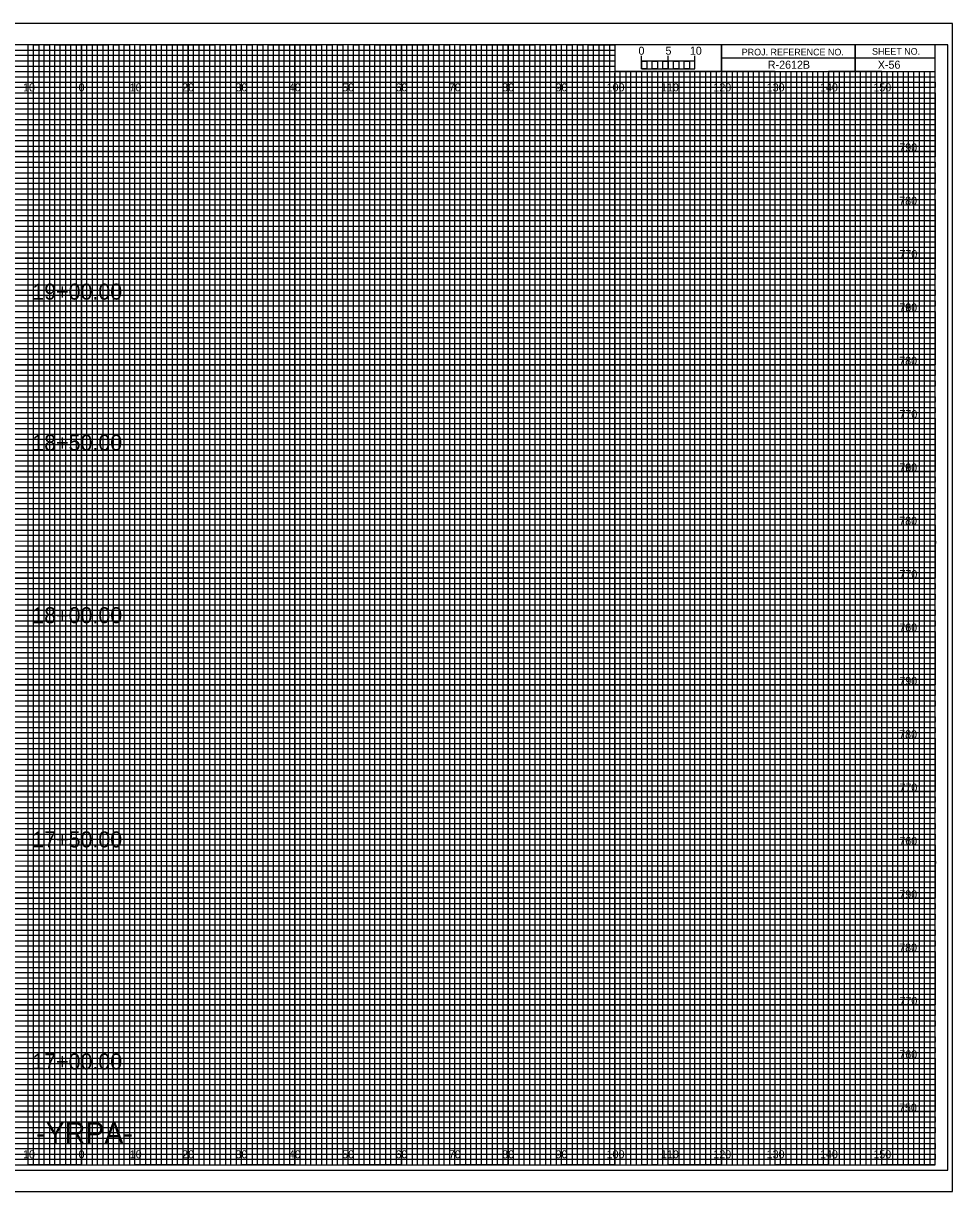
# Model space of a CAD drawing. Extents: x -13 to 323, y 655 to 874.
# Drawn here: x 149.1 to 323.3, y 655 to 874 of the extents above; entities that cross this region are included whole.
import ezdxf

# ---------------------------------------------------------------- set-up
doc = ezdxf.new("R2010")
doc.units = 0
for name, color, linetype in [('Exist Cross Section Cell', 7, 'Continuous'), ('Exist XS Ground Line', 7, 'Continuous'), ('Prop XS Ditch Slope Text', 7, 'Continuous'), ('Prop XS Ditch Standard Text', 7, 'Continuous'), ('Prop XS Dump Level', 7, 'Continuous'), ('Prop XS EOT Tick Mark', 7, 'Continuous'), ('Prop XS Finish Grade', 7, 'Continuous'), ('Prop XS Finish Grade Earthwork', 7, 'Continuous'), ('Prop XS Finish Grade Paved Shoulder', 7, 'Continuous'), ('Prop XS Finish Grade Pavement', 7, 'Continuous'), ('Prop XS Guardrail', 7, 'Continuous'), ('Prop XS Hydro Fill Slope Data', 7, 'Continuous'), ('Prop XS Pvmt Edge Slope', 7, 'Continuous'), ('Prop XS SE Text', 7, 'Continuous'), ('Prop XS Side Slope Text', 7, 'Continuous'), ('Prop XS SS Elevation Text', 7, 'Continuous'), ('Prop XS Subgrade Earthwork', 7, 'Continuous')]:
    doc.layers.add(name, color=color, linetype=linetype)

msp = doc.modelspace()

# ---------------------------------------------------------------- linework, layer by layer
at = {"layer": 'Exist XS Ground Line'}
for p, q in [((150, 870), (140, 870)), ((150, 660), (150, 870)), ((170, 870), (160, 870)), ((160, 870), (160, 660)), ((170, 660), (170, 870)), ((190, 870), (180, 870)), ((180, 870), (180, 660)), ((190, 660), (190, 870)), ((210, 870), (200, 870)), ((200, 870), (200, 660)), ((210, 660), (210, 870)), ((230, 870), (220, 870)), ((220, 870), (220, 660)), ((230, 660), (230, 870)), ((250, 870), (240, 870)), ((240, 870), (240, 660)), ((250, 660), (250, 870)), ((260, 870), (260, 660)), ((270, 660), (270, 865)), ((290, 865), (280, 865)), ((280, 865), (280, 660)), ((290, 660), (290, 865)), ((310, 865), (300, 865)), ((300, 865), (300, 660)), ((310, 660), (310, 865)), ((160, 660), (150, 660)), ((180, 660), (170, 660)), ((200, 660), (190, 660)), ((220, 660), (210, 660)), ((240, 660), (230, 660)), ((260, 660), (250, 660)), ((280, 660), (270, 660)), ((300, 660), (290, 660)), ((320, 660), (310, 660)), ((320, 660), (320, 660))]:
    msp.add_line(p, q, dxfattribs=at)
for points in [[(0, 860), (320, 860), (320, 850), (0, 850)], [(0, 840), (320, 840), (320, 830), (0, 830)], [(0, 820), (320, 820), (320, 810), (0, 810)], [(0, 800), (320, 800), (320, 790), (0, 790)], [(0, 780), (320, 780), (320, 770), (0, 770)], [(0, 760), (320, 760), (320, 750), (0, 750)], [(0, 740), (320, 740), (320, 730), (0, 730)], [(0, 720), (320, 720), (320, 710), (0, 710)], [(0, 700), (320, 700), (320, 690), (0, 690)], [(0, 680), (320, 680), (320, 670), (0, 670)]]:
    msp.add_lwpolyline(points, dxfattribs=at)
at = {"layer": 'Prop XS Ditch Slope Text'}
for p, q in [((305, 870), (305, 865)), ((305, 865), (305, 870)), ((280, 867.5), (280, 865)), ((320, 867.49), (280, 867.49)), ((280, 865), (320, 865))]:
    msp.add_line(p, q, dxfattribs=at)
for points in [[(320, 870), (0, 870), (0, 660), (320, 660)], [(280, 870), (260, 870), (260, 865.03), (280, 865.03)], [(320, 870), (280, 870), (280, 865), (320, 865)]]:
    msp.add_lwpolyline(points, close=True, dxfattribs=at)
at = {"layer": 'Prop XS Ditch Standard Text'}
for p, q in [((0, 869), (260, 869)), ((260, 867.98), (0, 867.98)), ((260, 869), (260, 867.98)), ((0, 867), (260, 867)), ((260, 865.89), (0, 865.89)), ((260, 867), (260, 865.89)), ((0, 864), (320, 864))]:
    msp.add_line(p, q, dxfattribs=at)
for points in [[(0, 863), (270, 863), (320, 863), (320, 862), (0, 862)], [(0, 861), (320, 861), (320, 859), (0, 859)], [(0, 858), (320, 858), (320, 857), (0, 856.98)], [(0, 856), (320, 856), (320, 854), (0, 854)], [(0, 853), (320, 853), (320, 852), (0, 852)], [(0, 851), (320, 851), (320, 849), (0, 849)], [(0, 848), (320, 848), (320, 847), (0, 847)], [(0, 846), (320, 846), (320, 844), (0, 844)], [(0, 843), (320, 843), (320, 842), (0, 842)], [(0, 841), (320, 841), (320, 839), (0, 839)], [(0, 838), (320, 838), (320, 837), (0, 837)], [(0, 836), (320, 836), (320, 833.95), (320, 833), (320, 832), (0, 832)], [(0, 834), (320, 834), (320, 833), (0, 833)], [(0, 831), (320, 831), (320, 829), (0, 829.03)], [(0, 829.03), (320, 829), (320, 828), (0, 828)], [(0, 827), (320, 827), (320, 826), (0, 826)], [(0, 824), (320, 824), (320, 823), (0, 823)], [(0, 822), (320, 822), (320, 821), (0, 821)], [(-0.07, 818.89), (320, 818.89), (320, 817.88), (-0.07, 817.88)], [(0, 817), (320, 817), (320, 816), (0, 816)], [(0, 814), (320, 814), (320, 813), (0, 813)], [(0, 812), (320, 812), (320, 811), (0, 811)], [(0, 809), (320, 809), (320, 808), (0, 808)], [(0, 807), (320, 807), (320, 806), (0, 806)], [(0, 804), (320, 804), (320, 803), (0, 803)], [(0, 802), (320, 802), (320, 801), (0, 801)], [(0, 799), (320, 799), (319.99, 797.98), (0, 798)], [(0, 797), (320, 797), (320, 796), (0, 796)], [(0, 794), (320, 794), (320, 793), (0, 793)], [(0, 792), (320, 792), (320, 791), (0, 791)], [(0, 789), (320, 789), (320, 788), (0, 788)], [(0, 787), (320, 787), (320, 786), (0, 786)], [(0, 784), (320, 784), (320, 783), (0, 783)], [(0, 782), (320, 782), (320, 781), (0, 781)], [(0, 779), (320, 779), (320, 778), (0, 778)], [(0, 776.99), (320.07, 776.91), (320, 776), (0, 776)], [(0, 774), (320, 774), (320, 773), (0, 773)], [(0, 772), (320, 772), (320, 771), (0, 771)], [(0, 769), (320, 769), (320, 768), (0, 768)], [(0, 767), (320, 767), (320, 766), (0, 766)], [(0, 764), (320, 764), (320, 763), (0, 763)], [(0, 762), (320, 762), (320, 761), (0, 761)], [(0, 759), (320, 759), (320, 758), (0, 758)], [(0, 757), (320, 757), (320, 756), (0, 756)], [(0, 754), (320, 754), (320, 753), (0, 753)], [(0, 752), (320, 752), (320, 751), (0, 751)], [(0, 749), (320, 749), (320, 748), (0, 748)], [(0, 747), (320, 747), (320, 746), (0, 746)], [(0, 744), (320, 744), (320, 743), (0, 743)], [(0, 742), (320, 742), (320, 741), (0, 741)], [(0, 739), (320, 739), (319.99, 737.98), (0, 738)], [(0, 737), (320, 737), (320, 736), (0, 736)], [(0, 734), (320, 734), (320, 733), (0, 733)], [(0, 732), (320, 732), (320, 731), (0, 731)], [(0, 729), (320, 729), (320, 728), (0, 728)], [(0, 727), (320, 727), (320, 726), (0, 726)], [(0, 724), (320, 724), (320, 723), (0, 723)], [(0, 722), (320, 722), (320, 721), (0, 721)], [(0, 719), (320, 719), (320, 718), (0, 718)], [(0, 716.99), (320.07, 716.91), (320, 716), (0, 716)], [(0, 714), (320, 714), (320, 713), (0, 713)], [(0, 712), (320, 712), (320, 711), (0, 711)], [(0, 709), (320, 709), (320, 708), (0, 708)], [(0, 707), (320, 707), (320, 706), (0, 706)], [(0, 704), (320, 704), (320, 703), (0, 703)], [(0, 702), (320, 702), (320, 701), (0, 701)], [(0, 699), (320, 699), (320, 698), (0, 698)], [(0, 697), (320, 697), (320, 696), (0, 696)], [(0, 694), (320, 694), (320, 693), (0, 693)], [(0, 692), (320, 692), (320, 691), (0, 691)], [(0, 689), (320, 689), (320, 688), (0, 688)], [(0, 687), (320, 687), (320, 686), (0, 686)], [(0, 684), (320, 684), (320, 683), (0, 683)], [(0, 682), (320, 682), (320, 681), (0, 681)], [(0, 679), (320, 679), (320, 678), (0, 678)], [(0, 677), (320, 677), (320, 676), (0, 676)], [(0, 674), (320, 674), (320, 673), (0, 673)], [(0, 672), (320, 672), (320, 671), (0, 671)], [(0, 669), (320, 669), (320, 668), (0, 668)], [(0, 667), (320, 667), (320, 666), (0, 666)], [(0, 664), (320, 664), (320, 663), (0, 663)], [(0, 662), (320, 662), (320, 661), (0, 661)]]:
    msp.add_lwpolyline(points, dxfattribs=at)
at = {"layer": 'Prop XS Dump Level'}
for points in [[(145, 660), (155, 660), (155, 870), (165, 870), (165, 660), (175, 660), (175, 870), (185, 870), (185, 660), (195, 660), (195, 870), (205, 870), (205, 660), (215, 660), (215, 870), (225, 870), (225, 660), (235, 660), (235, 870), (245, 870), (245, 660), (255, 660), (255, 870), (259.93, 870), (260, 870), (260, 865), (264.99, 865), (264.99, 660), (275, 660), (275, 865), (285, 865), (285, 660), (295, 660), (295, 865), (305, 865), (305, 660), (315, 660), (315, 865)], [(0, 865), (275, 865)], [(0, 845), (320, 845), (320, 855), (0, 855)], [(0, 825), (320, 825), (320, 835), (0, 835)], [(0, 805), (320, 805), (320, 815), (0, 815)], [(0, 785), (320, 785), (320, 795), (0, 795)], [(0, 765), (320, 765), (320, 775), (0, 775)], [(0, 745), (320, 745), (320, 755), (0, 755)], [(0, 725), (320, 725), (320, 735), (0, 735)], [(0, 705), (320, 705), (320, 715), (0, 715)], [(0, 685), (320, 685), (320, 695), (0, 695)], [(0, 665), (320, 665), (320, 675), (0, 675)]]:
    msp.add_lwpolyline(points, dxfattribs=at)
at = {"layer": 'Prop XS Finish Grade'}
for p, q in [((150, 660), (150, 870)), ((160, 660), (160, 870)), ((170, 660), (170, 870)), ((180, 660), (180, 870)), ((190, 660), (190, 870)), ((200, 660), (200, 870)), ((210, 660), (210, 870)), ((220, 660), (220, 870)), ((230, 660), (230, 870)), ((240, 660), (240, 870)), ((250, 660), (250, 870)), ((260, 660), (260, 864.69)), ((270, 660), (270, 864.69)), ((280, 660), (280, 864.69)), ((290, 660), (290, 864.69)), ((300, 660), (300, 864.69)), ((310, 660), (310, 864.69)), ((0, 860), (320, 860)), ((0, 850), (320, 850)), ((0, 840), (320, 840)), ((0, 830), (320, 830)), ((0, 820), (320, 820)), ((0, 810), (320, 810)), ((0, 800), (320, 800)), ((0, 790), (320, 790)), ((0, 780), (320, 780)), ((0, 770), (320, 770)), ((0, 760), (320, 760)), ((0, 750), (320, 750)), ((0, 740), (320, 740)), ((0, 730), (320, 730)), ((0, 720), (320, 720)), ((0, 710), (320, 710)), ((0, 700), (320, 700)), ((0, 690), (320, 690)), ((0, 680), (320, 680)), ((0, 670), (320, 670))]:
    msp.add_line(p, q, dxfattribs=at)
at = {"layer": 'Prop XS Finish Grade Earthwork'}
msp.add_lwpolyline([(-13.4, 655), (323.3, 655), (323.3, 874), (-13.4, 874)], close=True, dxfattribs=at)
at = {"layer": 'Prop XS Pvmt Edge Slope'}
for p, q in [((323.3, 874), (-13.4, 874)), ((-13.4, 655), (323.3, 655))]:
    msp.add_line(p, q, dxfattribs=at)
at = {"layer": 'Prop XS Side Slope Text'}
for p, q in [((267, 865), (266.01, 865)), ((266.01, 865), (266.01, 660)), ((267, 660), (267, 865)), ((269, 865), (268, 865)), ((268, 865), (268, 660)), ((269, 660), (269, 865)), ((266.01, 660), (265, 660)), ((268, 660), (267, 660))]:
    msp.add_line(p, q, dxfattribs=at)
for points in [[(150, 660), (151, 660), (151, 870), (152, 870), (152, 660)], [(152, 660), (153, 660), (153, 870), (154, 870), (154, 660)], [(155, 660), (156, 660), (156, 870), (157, 870), (157, 660)], [(157, 660), (158, 660), (158, 870), (159, 870), (159, 660)], [(160, 660), (161, 660), (161, 870), (162, 870), (162, 660)], [(162, 660), (163, 660), (163, 870), (164, 870), (164, 660)], [(165, 660), (166, 660), (166, 870), (167, 870), (167, 660)], [(167, 660), (168, 660), (168, 870), (169, 870), (169, 660)], [(170, 660), (171, 660), (171, 870), (172, 870), (172, 660)], [(172, 660), (173, 660), (173, 870), (174, 870), (174, 660)], [(175, 660), (176, 660), (176, 870), (177, 870), (177, 660)], [(177, 660), (178, 660), (178, 870), (179, 870), (179, 660)], [(180, 660), (181, 660), (181, 870), (182, 870), (182, 660)], [(182, 660), (183, 660), (183, 870), (184, 870), (184, 660)], [(185, 660), (186, 660), (186, 870), (187, 870), (187, 660)], [(187, 660), (188, 660), (188, 870), (189, 870), (189, 660)], [(190, 660), (191, 660), (191, 870), (192, 870), (192, 660)], [(192, 660), (193, 660), (193, 870), (194, 870), (194, 660)], [(195, 660), (196, 660), (196, 870), (197, 870), (197, 660)], [(197, 660), (198, 660), (198, 870), (199, 870), (199, 660)], [(200, 660), (201, 660), (201, 870), (202, 870), (202, 660)], [(202, 660), (203, 660), (203, 870), (204, 870), (204, 660)], [(205, 660), (206, 660), (206, 870), (207, 870), (207, 660)], [(207, 660), (208, 660), (208, 870), (209, 870), (209, 660)], [(210, 660), (211, 660), (211, 870), (212, 870), (212, 660)], [(212, 660), (213, 660), (213, 870), (214, 870), (214, 660)], [(215, 660), (216, 660), (216, 870), (217, 870), (217, 660)], [(217, 660), (218, 660), (218, 870), (219, 870), (219, 660)], [(220, 660), (221, 660), (221, 870), (222, 870), (222, 660)], [(222, 660), (223, 660), (223, 870), (224, 870), (224, 660)], [(225, 660), (226, 660), (226, 870), (227, 870), (227, 660)], [(227, 660), (228, 660), (228, 870), (229, 870), (229, 660)], [(230, 660), (231, 660), (231, 870), (232, 870), (232, 660)], [(232, 660), (233, 660), (233, 870), (234, 870), (234, 660)], [(235, 660), (236, 660), (236, 870), (237, 870), (237, 660)], [(237, 660), (238, 660), (238, 870), (239, 870), (239, 660)], [(240, 660), (241, 660), (241, 870), (242, 870), (242, 660)], [(242, 660), (243, 660), (243, 870), (244, 870), (244, 660)], [(245, 660), (246, 660), (246, 870), (247, 870), (247, 660)], [(247, 660), (248, 660), (248, 870), (249, 870), (249, 660)], [(250, 660), (251, 660), (251, 870), (252, 870), (252, 660)], [(252, 660), (253, 660), (253, 870), (254, 870), (254, 660)], [(255, 660), (256, 660), (256, 870), (257, 870), (257, 660)], [(257, 660), (258, 660), (258, 870), (259, 870), (259, 660)], [(260, 660), (261, 660), (261, 865), (262.02, 865), (262.02, 660)], [(262, 660), (263, 660), (263, 865), (263.99, 865), (263.99, 660)], [(270, 660), (270.98, 660), (270.98, 865), (272, 865), (272, 660)], [(272, 660), (273, 660), (273, 865), (274.05, 865), (274.05, 660)], [(275, 660), (276, 660), (276, 865), (277, 865), (277, 660)], [(277, 660), (278, 660), (278, 865), (279, 865), (279, 660)], [(280, 660), (281, 660), (281, 865), (282, 865), (282, 660)], [(282, 660), (283, 660), (283, 865), (284, 865), (284, 660)], [(285, 660), (286, 660), (286, 865), (287, 865), (287, 660)], [(287, 660), (288, 660), (288, 865), (289, 865), (289, 660)], [(290, 660), (291, 660), (291, 865), (292, 865), (292, 660)], [(292, 660), (293, 660), (293, 865), (294, 865), (294, 660)], [(295, 660), (296, 660), (296, 865), (297, 865), (297, 660)], [(297, 660), (298, 660), (298, 865), (299, 865), (299, 660)], [(300, 660), (301, 660), (301, 865), (302, 865), (302, 660)], [(302, 660), (303, 660), (303, 865), (304, 865), (304, 660)], [(305, 660), (306, 660), (306, 865), (307, 865), (307, 660)], [(307, 660), (308, 660), (308, 865), (309, 865), (309, 660)], [(310, 660), (311, 660), (311, 865), (312, 865), (312, 660)], [(312, 660), (313, 660), (313, 865), (314, 865), (314, 660)], [(315, 660), (316, 660), (316, 865), (317, 865), (317, 660)], [(317, 660), (318, 660), (318, 865), (319, 865), (319, 660)]]:
    msp.add_lwpolyline(points, dxfattribs=at)
at = {"layer": 'Prop XS SS Elevation Text'}
for p, q in [((265, 865.49), (265, 867.9)), ((265, 866.9), (265, 867.9)), ((270, 865.49), (270, 867.9)), ((275, 865.49), (275, 867.9)), ((275, 866.9), (275, 867.9))]:
    msp.add_line(p, q, dxfattribs=at)
for points in [[(275, 866.9), (265, 866.9), (265, 865.49), (275, 865.49)], [(265, 866.9), (266, 866.9), (266, 865.49), (265, 865.49)], [(267, 866.9), (268, 866.9), (268, 865.49), (267, 865.49)], [(269, 866.9), (270, 866.9), (270, 865.49), (269, 865.49)], [(271, 866.9), (272, 866.9), (272, 865.49), (271, 865.49)], [(273, 866.9), (274, 866.9), (274, 865.49), (273, 865.49)]]:
    msp.add_lwpolyline(points, close=True, dxfattribs=at)
at = {"layer": 'Prop XS Subgrade Earthwork'}
msp.add_lwpolyline([(-10.8, 659), (322.4, 659), (322.4, 870), (-10.8, 870)], close=True, dxfattribs=at)

# ---------------------------------------------------------------- texts
at = {"layer": 'Exist Cross Section Cell'}
for s, p in [('10', (149.04, 861.25)), ('0', (159.45, 861.25)), ('0', (159.45, 861.25)), ('10', (169.04, 861.25)), ('20', (178.86, 861.25)), ('30', (188.86, 861.25)), ('40', (198.86, 861.25)), ('50', (208.86, 861.25)), ('60', (218.86, 861.25)), ('70', (228.86, 861.25)), ('80', (238.86, 861.25)), ('90', (248.86, 861.25)), ('100', (258.44, 861.25)), ('110', (268.62, 861.25)), ('120', (278.44, 861.25)), ('130', (288.44, 861.25)), ('140', (298.44, 861.25)), ('150', (308.44, 861.25)), ('10', (149.04, 661.25)), ('0', (159.45, 661.25)), ('0', (159.45, 661.25)), ('10', (169.04, 661.25)), ('20', (178.86, 661.25)), ('30', (188.86, 661.25)), ('40', (198.86, 661.25)), ('50', (208.86, 661.25)), ('60', (218.86, 661.25)), ('70', (228.86, 661.25)), ('80', (238.86, 661.25)), ('90', (248.86, 661.25)), ('100', (258.44, 661.25)), ('110', (268.62, 661.25)), ('120', (278.44, 661.25)), ('130', (288.44, 661.25)), ('140', (298.44, 661.25)), ('150', (308.44, 661.25))]:
    msp.add_text(s, height=1.5, dxfattribs=at).set_placement(p)
at = {"layer": 'Prop XS Ditch Slope Text'}
for s, p in [('PROJ. REFERENCE NO.', (283.77, 867.99)), ('SHEET NO.', (308.19, 868.12))]:
    msp.add_text(s, height=1.25, dxfattribs=at).set_placement(p)
at = {"layer": 'Prop XS EOT Tick Mark'}
for s, p in [('790', (313.3, 850)), ('780', (313.28, 840)), ('770', (313.33, 830)), ('790', (313.3, 820)), ('760', (313.3, 820)), ('780', (313.28, 810)), ('770', (313.33, 800)), ('790', (313.3, 790)), ('760', (313.3, 790)), ('780', (313.28, 780)), ('770', (313.33, 770)), ('760', (313.3, 760)), ('790', (313.3, 750)), ('780', (313.28, 740)), ('770', (313.33, 730)), ('760', (313.3, 720)), ('790', (313.3, 710)), ('780', (313.28, 700)), ('770', (313.33, 690)), ('760', (313.3, 680)), ('750', (313.25, 670))]:
    msp.add_text(s, height=1.5, dxfattribs=at).set_placement(p)
at = {"layer": 'Prop XS Finish Grade Paved Shoulder'}
msp.add_text('-YRPA-', height=4, dxfattribs=at).set_placement((151.5, 664))
at = {"layer": 'Prop XS Finish Grade Pavement'}
msp.add_text('X-56', height=1.5, dxfattribs=at).set_placement((309.27, 865.5))
at = {"layer": 'Prop XS Guardrail'}
msp.add_text('R-2612B', height=1.5, dxfattribs=at).set_placement((288.66, 865.5))
at = {"layer": 'Prop XS Hydro Fill Slope Data'}
for s, p in [('5', (269.47, 868.12)), ('10', (274.04, 868.12))]:
    msp.add_text(s, height=1.5, dxfattribs=at).set_placement(p)
at = {"layer": 'Prop XS SE Text'}
for s, p in [('19+00.00', (150.77, 822.21)), ('18+50.00', (150.77, 793.91)), ('18+00.00', (150.77, 761.56)), ('17+50.00', (150.77, 719.53)), ('17+00.00', (150.77, 677.9))]:
    msp.add_text(s, height=3, dxfattribs=at).set_placement(p)
at = {"layer": 'Prop XS SS Elevation Text'}
msp.add_text('0', height=1.5, dxfattribs=at).set_placement((264.41, 868.12))

doc.saveas('drawing.dxf')
